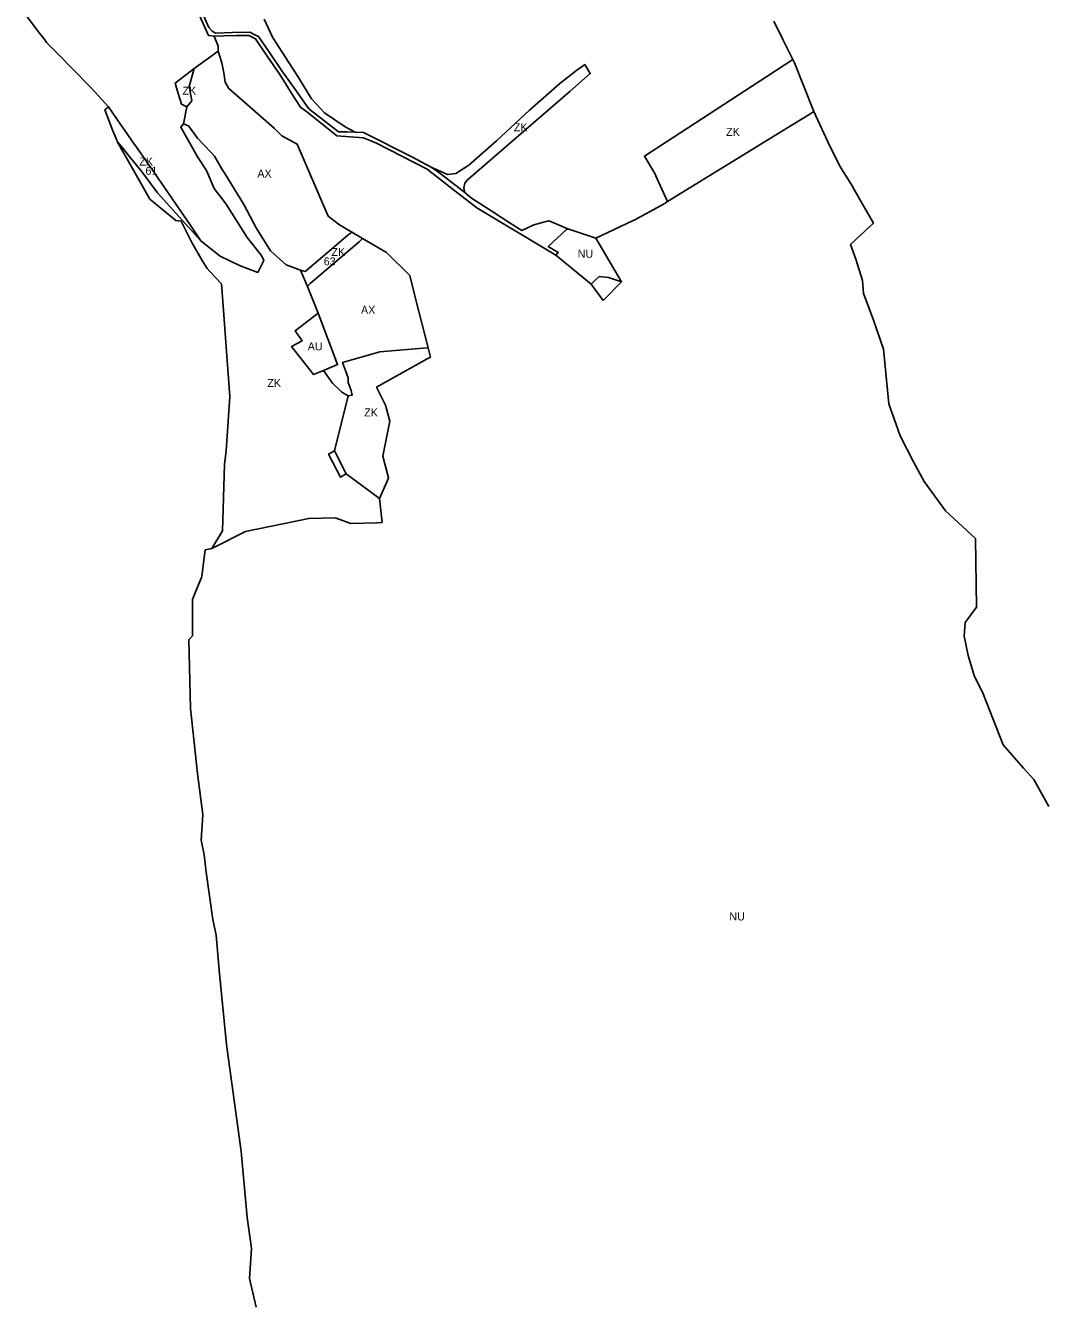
# Model space of a CAD drawing. Extents: x -521939 to -516426, y -1197857 to -1189551.
# Drawn here: x -518965 to -517696, y -1196257 to -1194658 of the extents above; entities that cross this region are included whole.
import ezdxf

# ---------------------------------------------------------------- set-up
doc = ezdxf.new("R2010")
doc.units = 0
for name, color, linetype in [('90710013', 7, 'Continuous'), ('90710023', 7, 'Continuous'), ('90730013', 7, 'Continuous'), ('90750013', 7, 'Continuous'), ('90760013', 7, 'Continuous'), ('ID_navrh', 7, 'Continuous')]:
    doc.layers.add(name, color=color, linetype=linetype)

msp = doc.modelspace()

# ---------------------------------------------------------------- linework, layer by layer
at = {"layer": '90710013'}
for points in [[(-518416.02, -1194866.37), (-518417.07, -1194860.7), (-518415.72, -1194854.89), (-518413.12, -1194851.17), (-518284.47, -1194739.67), (-518259.19, -1194717.76), (-518265.96, -1194706.53), (-518275.98, -1194713.4), (-518297.28, -1194730.31), (-518335.14, -1194763.37), (-518376.44, -1194801.94), (-518410.77, -1194832.23), (-518426.93, -1194842.54), (-518437.35, -1194843.87), (-518458.12, -1194834.75), (-518449.87, -1194840.31), (-518440.03, -1194847.7), (-518416.02, -1194866.37)], [(-517979.82, -1194765.19), (-517992.62, -1194732.87), (-518003.98, -1194704.16), (-518006.01, -1194700.12), (-518038.54, -1194721.31), (-518191.58, -1194821), (-518178.44, -1194842.76), (-518174.42, -1194852.09), (-518162.69, -1194877.72), (-518006.26, -1194781.46), (-517984.97, -1194768.36), (-517979.82, -1194765.19)], [(-518763.14, -1194759.44), (-518757.06, -1194751.97), (-518760.47, -1194734.12), (-518754.1, -1194711.5), (-518754.1, -1194711.49), (-518777.63, -1194729.6), (-518773.9, -1194742.58), (-518770.01, -1194755.88), (-518763.14, -1194759.44)], [(-518578.9, -1195189.46), (-518561.85, -1195120.59), (-518569.49, -1195116.16), (-518581.19, -1195104.89), (-518592.62, -1195088.86), (-518604.93, -1195093.93), (-518632.37, -1195058.71), (-518619.09, -1195051.71), (-518627.9, -1195039.34), (-518599.15, -1195017.18), (-518603.33, -1195006.68), (-518612.46, -1194983.75), (-518621.14, -1194963.55), (-518639.03, -1194956.62), (-518658.6, -1194939.28), (-518676.38, -1194910.65), (-518692.19, -1194881.36), (-518715.84, -1194842.65), (-518718.88, -1194837.59), (-518728.73, -1194821.13), (-518733.74, -1194815.77), (-518749.9, -1194798.59), (-518761.09, -1194783.03), (-518767.51, -1194780.53), (-518770.85, -1194784.96), (-518750.08, -1194821.88), (-518738.64, -1194838.92), (-518729.05, -1194861.24), (-518713.96, -1194880.83), (-518687.89, -1194922.47), (-518669.78, -1194944.97), (-518667.07, -1194951.45), (-518674.42, -1194966.29), (-518697.27, -1194957.86), (-518721.6, -1194945.89), (-518745.52, -1194926.78), (-518800.02, -1194866.93), (-518820.29, -1194839.32), (-518835.53, -1194820.44), (-518843.34, -1194811.13), (-518850.19, -1194802.69), (-518820.69, -1194854.64), (-518809.32, -1194874.65), (-518776.75, -1194901.38), (-518770.47, -1194902.08), (-518757.12, -1194929), (-518744.12, -1194951.55), (-518737.6, -1194961.57), (-518734.46, -1194964.98), (-518720.07, -1194980.61), (-518718.38, -1195002.82), (-518709.39, -1195121.23), (-518713.87, -1195189.36), (-518716.08, -1195206.38), (-518718.82, -1195289.08), (-518731.97, -1195311.31), (-518690.03, -1195290), (-518610.94, -1195273.71), (-518577.83, -1195273), (-518558.14, -1195280.21), (-518526.44, -1195279.07), (-518519.2, -1195278.81), (-518522.38, -1195248.79), (-518563.97, -1195218.15), (-518571.3, -1195222), (-518586.21, -1195193.27), (-518578.9, -1195189.46)], [(-518578.9, -1195189.46), (-518563.97, -1195218.15), (-518522.38, -1195248.79), (-518513.12, -1195227.2), (-518511.27, -1195222.88), (-518518.19, -1195195.9), (-518509.49, -1195152.1), (-518514.93, -1195132.02), (-518526.18, -1195109.58), (-518462.79, -1195074.28), (-518458.85, -1195072.09), (-518461.82, -1195060.41), (-518468.55, -1195061.01), (-518522.17, -1195065.75), (-518568.86, -1195079.07), (-518561.77, -1195097.95), (-518561.65, -1195103.95), (-518557.91, -1195113.9), (-518556.68, -1195119.84), (-518561.85, -1195120.59), (-518578.9, -1195189.46)]]:
    msp.add_lwpolyline(points, dxfattribs=at)
at = {"layer": '90710023'}
for points in [[(-518850.19, -1194802.69), (-518843.34, -1194811.13), (-518835.53, -1194820.44), (-518820.29, -1194839.32), (-518800.02, -1194866.93), (-518745.52, -1194926.78), (-518758.18, -1194908.03), (-518809.54, -1194833.7), (-518824.2, -1194812.48), (-518831.36, -1194802.11), (-518838.55, -1194791.71), (-518845.5, -1194781.65), (-518860.9, -1194759.36), (-518865.86, -1194763.22), (-518855.5, -1194789.32), (-518850.84, -1194801.06), (-518850.19, -1194802.69)], [(-518557.27, -1194915.81), (-518559.35, -1194917.65), (-518561.44, -1194919.5), (-518588.48, -1194942.32), (-518615.53, -1194965.15), (-518621.14, -1194963.55), (-518612.46, -1194983.75), (-518609.05, -1194980.13), (-518578.49, -1194954.01), (-518547.93, -1194927.89), (-518543.87, -1194923.75), (-518557.27, -1194915.81)]]:
    msp.add_lwpolyline(points, dxfattribs=at)
at = {"layer": '90730013'}
for points in [[(-518749.75, -1194628.33), (-518735.68, -1194660.28), (-518731.66, -1194664.89), (-518727.55, -1194667.14), (-518706.04, -1194666.63), (-518684.53, -1194666.12), (-518679.04, -1194668.76), (-518673.54, -1194671.4), (-518658.98, -1194692.9), (-518644.41, -1194714.39), (-518627.58, -1194738.16), (-518610.75, -1194761.93), (-518592.32, -1194776.2), (-518573.88, -1194790.47), (-518563.47, -1194790.77), (-518553.06, -1194791.06), (-518565.58, -1194784.24), (-518591.06, -1194766.84), (-518607.41, -1194749.43), (-518623.89, -1194722.86), (-518656.27, -1194672.17), (-518666.51, -1194649.62)], [(-517686.33, -1195633.83), (-517705.09, -1195599.86), (-517718.01, -1195585.89), (-517743.18, -1195556.56), (-517768.13, -1195492.77), (-517779.75, -1195470.04), (-517786.92, -1195445.13), (-517791.97, -1195421.06), (-517790.61, -1195404.02), (-517776.69, -1195384.65), (-517777.74, -1195299), (-517815.27, -1195264.33), (-517841.99, -1195227.55), (-517855.27, -1195202.9), (-517872.07, -1195170.61), (-517886.13, -1195130.55), (-517892.85, -1195062.16), (-517905.77, -1195024.59), (-517918.02, -1194992.59), (-517919.16, -1194976.41), (-517927.44, -1194949.61), (-517934.18, -1194931.51), (-517910.02, -1194908.82), (-517905.52, -1194904.59), (-517920.71, -1194877.9), (-517933.13, -1194856.07), (-517947.22, -1194833.42), (-517962.22, -1194803.3), (-517979.82, -1194765.19), (-517984.97, -1194768.36), (-518006.26, -1194781.46), (-518162.69, -1194877.72), (-518167.76, -1194880.84), (-518203.35, -1194900.68), (-518206.51, -1194901.69), (-518252.06, -1194923.56), (-518220.17, -1194977.86), (-518242.88, -1195001.36), (-518257.99, -1194980.81), (-518302.06, -1194944.78), (-518400.82, -1194885.57), (-518428.24, -1194864.28), (-518463.01, -1194837.27), (-518526.37, -1194804.79), (-518542.69, -1194798.26), (-518575.86, -1194795.7), (-518611.71, -1194766.87), (-518621.23, -1194759.93), (-518631.9, -1194743.01), (-518639.9, -1194730.32), (-518647.9, -1194717.64), (-518662.7, -1194695.92), (-518677.5, -1194674.21), (-518685.8, -1194670.06), (-518701.17, -1194670.37), (-518716.54, -1194670.67), (-518729.2, -1194670.98), (-518724.12, -1194683.6), (-518723.86, -1194689.63), (-518719.62, -1194704.53), (-518717.06, -1194716.71), (-518715.14, -1194728.52), (-518710.66, -1194736.6), (-518654.08, -1194786.18), (-518644.64, -1194795.63), (-518625.17, -1194805.96), (-518586.43, -1194895.87), (-518572.38, -1194906.86), (-518557.27, -1194915.81), (-518543.87, -1194923.75), (-518513.79, -1194941.58), (-518484.79, -1194970.06), (-518477.04, -1195000.54), (-518461.82, -1195060.41), (-518458.85, -1195072.09), (-518462.79, -1195074.28), (-518526.18, -1195109.58), (-518514.93, -1195132.02), (-518509.49, -1195152.1), (-518518.19, -1195195.9), (-518511.27, -1195222.88), (-518513.12, -1195227.2), (-518522.38, -1195248.79), (-518519.2, -1195278.81), (-518526.44, -1195279.07), (-518558.14, -1195280.21), (-518577.83, -1195273), (-518610.94, -1195273.71), (-518690.03, -1195290), (-518731.97, -1195311.31), (-518740.14, -1195312.89), (-518744.35, -1195345.93), (-518744.97, -1195347.47), (-518750.12, -1195360.34), (-518756.03, -1195375.1), (-518756, -1195391.6), (-518755.96, -1195420.36), (-518760.89, -1195425.68), (-518758.62, -1195511.5), (-518749.83, -1195592.65), (-518743.14, -1195643.78), (-518745.32, -1195675.95), (-518741.37, -1195694.14), (-518739.22, -1195715.86), (-518730.8, -1195775.07), (-518726.63, -1195794.44), (-518722.87, -1195838.39), (-518713.59, -1195931.36), (-518695.49, -1196064.81), (-518687.78, -1196147.53), (-518682.4, -1196186.23), (-518684.91, -1196223.86), (-518676.71, -1196259.65)], [(-518220.17, -1194977.86), (-518252.06, -1194923.56), (-518287.17, -1194911.99), (-518288.68, -1194912.69), (-518311.68, -1194933.74), (-518299.16, -1194941.37), (-518302.06, -1194944.78), (-518257.99, -1194980.81), (-518253, -1194976.13), (-518248.01, -1194971.45), (-518236.28, -1194972.79), (-518220.17, -1194977.86)]]:
    msp.add_lwpolyline(points, dxfattribs=at)
at = {"layer": '90750013'}
msp.add_lwpolyline([(-518592.62, -1195088.86), (-518574.89, -1195081.56), (-518599.15, -1195017.18), (-518627.9, -1195039.34), (-518619.09, -1195051.71), (-518632.37, -1195058.71), (-518604.93, -1195093.93), (-518592.62, -1195088.86)], dxfattribs=at)
at = {"layer": '90760013'}
for points in [[(-518964.64, -1194644.1), (-518948.85, -1194665.08), (-518940.77, -1194675.83), (-518938.39, -1194678.98), (-518936.08, -1194681.32), (-518931.88, -1194685.59), (-518927.87, -1194689.65), (-518919.46, -1194698.18), (-518909, -1194708.78), (-518902.77, -1194715.1), (-518896.97, -1194720.99), (-518892.56, -1194725.55), (-518883.3, -1194735.11), (-518878.45, -1194740.13), (-518860.9, -1194759.36), (-518845.5, -1194781.65), (-518838.55, -1194791.71), (-518831.36, -1194802.11), (-518824.2, -1194812.48), (-518809.54, -1194833.7), (-518758.18, -1194908.03), (-518745.52, -1194926.78), (-518721.6, -1194945.89), (-518697.27, -1194957.86), (-518674.42, -1194966.29), (-518667.07, -1194951.45), (-518669.78, -1194944.97), (-518687.89, -1194922.47), (-518713.96, -1194880.83), (-518729.05, -1194861.24), (-518738.64, -1194838.92), (-518750.08, -1194821.88), (-518770.85, -1194784.96), (-518767.51, -1194780.53), (-518763.14, -1194759.44)], [(-518763.14, -1194759.44), (-518770.01, -1194755.88), (-518773.9, -1194742.58), (-518777.63, -1194729.6), (-518754.1, -1194711.49), (-518723.86, -1194689.63), (-518724.12, -1194683.6), (-518729.2, -1194670.98), (-518736.23, -1194670.16), (-518749.32, -1194640.47)], [(-518666.51, -1194649.62), (-518656.27, -1194672.17), (-518623.89, -1194722.86), (-518607.41, -1194749.43), (-518591.06, -1194766.84), (-518565.58, -1194784.24), (-518553.06, -1194791.06), (-518542.37, -1194791.36), (-518481.99, -1194821.99), (-518458.12, -1194834.75), (-518437.35, -1194843.87), (-518426.93, -1194842.54), (-518410.77, -1194832.23), (-518376.44, -1194801.94), (-518335.14, -1194763.37), (-518297.28, -1194730.31), (-518275.98, -1194713.4), (-518265.96, -1194706.53), (-518259.19, -1194717.76), (-518284.47, -1194739.67), (-518413.12, -1194851.17), (-518415.72, -1194854.89), (-518417.07, -1194860.7), (-518416.02, -1194866.37), (-518407.42, -1194873.57), (-518380.99, -1194890.59), (-518359.22, -1194904.68), (-518344.66, -1194913.71), (-518329.66, -1194906.93), (-518311.54, -1194901.71), (-518309.69, -1194902.16), (-518287.17, -1194911.99), (-518252.06, -1194923.56), (-518206.51, -1194901.69), (-518203.35, -1194900.68), (-518167.76, -1194880.84), (-518162.69, -1194877.72), (-518174.42, -1194852.09), (-518178.44, -1194842.76), (-518191.58, -1194821), (-518038.54, -1194721.31), (-518006.01, -1194700.12), (-518018.4, -1194675.4), (-518029.91, -1194652.44)], [(-518763.14, -1194759.44), (-518767.51, -1194780.53), (-518761.09, -1194783.03), (-518749.9, -1194798.59), (-518733.74, -1194815.77), (-518728.73, -1194821.13), (-518718.88, -1194837.59), (-518715.84, -1194842.65), (-518692.19, -1194881.36), (-518676.38, -1194910.65), (-518658.6, -1194939.28), (-518639.03, -1194956.62), (-518621.14, -1194963.55), (-518615.53, -1194965.15), (-518588.48, -1194942.32), (-518561.44, -1194919.5), (-518559.35, -1194917.65), (-518557.27, -1194915.81), (-518572.38, -1194906.86), (-518586.43, -1194895.87), (-518625.17, -1194805.96), (-518644.64, -1194795.63), (-518654.08, -1194786.18), (-518710.66, -1194736.6), (-518715.14, -1194728.52), (-518717.06, -1194716.71), (-518719.62, -1194704.53), (-518723.86, -1194689.63), (-518754.1, -1194711.49), (-518754.1, -1194711.5), (-518760.47, -1194734.12), (-518757.06, -1194751.97), (-518763.14, -1194759.44)], [(-518561.85, -1195120.59), (-518556.68, -1195119.84), (-518557.91, -1195113.9), (-518561.65, -1195103.95), (-518561.77, -1195097.95), (-518568.86, -1195079.07), (-518522.17, -1195065.75), (-518468.55, -1195061.01), (-518461.82, -1195060.41), (-518477.04, -1195000.54), (-518484.79, -1194970.06), (-518513.79, -1194941.58), (-518543.87, -1194923.75), (-518547.93, -1194927.89), (-518578.49, -1194954.01), (-518609.05, -1194980.13), (-518612.46, -1194983.75), (-518603.33, -1195006.68), (-518599.15, -1195017.18), (-518574.89, -1195081.56), (-518592.62, -1195088.86), (-518581.19, -1195104.89), (-518569.49, -1195116.16), (-518561.85, -1195120.59)]]:
    msp.add_lwpolyline(points, dxfattribs=at)

# ---------------------------------------------------------------- texts
at = {"layer": '90710013'}
for rotation, p in [(360, (-518768.67, -1194744.2)), (0, (-518089.47, -1194795.69)), (0, (-518662.66, -1195109.47)), (0, (-518541.65, -1195146.27))]:
    msp.add_text('ZK', height=10, rotation=rotation, dxfattribs=at).set_placement(p)
msp.add_text('ZK', height=10, dxfattribs=at).set_placement((-518354.77, -1194789.84))
at = {"layer": '90710023'}
for rotation, p in [(360, (-518822.54, -1194832.71)), (0, (-518582.57, -1194945.72))]:
    msp.add_text('ZK', height=10, rotation=rotation, dxfattribs=at).set_placement(p)
at = {"layer": '90730013'}
for p in [(-518274.9, -1194947.95), (-518085.4, -1195776.17)]:
    msp.add_text('NU', height=10, rotation=360, dxfattribs=at).set_placement(p)
at = {"layer": '90750013'}
msp.add_text('AU', height=10, rotation=360, dxfattribs=at).set_placement((-518612.19, -1195063.67))
at = {"layer": '90760013'}
for rotation, p in [(0, (-518675.06, -1194847.71)), (360, (-518545.58, -1195018.05))]:
    msp.add_text('AX', height=10, rotation=rotation, dxfattribs=at).set_placement(p)
at = {"layer": 'ID_navrh'}
for s, p in [('61', (-518814.88, -1194844.27)), ('63', (-518592.21, -1194957.51))]:
    msp.add_text(s, height=10, rotation=0, dxfattribs=at).set_placement(p)

doc.saveas('drawing.dxf')
